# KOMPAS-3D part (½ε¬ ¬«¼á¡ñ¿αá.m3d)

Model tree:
1. Эскиз:1
2. Операция выдавливания:1
     Расстояние 1 = 4.8; Расстояние 2 = 0.3
3. Скругление:1
     Радиус = 14
4. Эскиз:3
5. Вырезать элемент выдавливания:1
     Расстояние 1 = 14.5
6. Эскиз:32
7. Операция выдавливания:21
     Расстояние 1 = 2; Расстояние 2 = 0.3
8. Эскиз:33
9. Операция выдавливания:22
     Расстояние 1 = 2; Расстояние 2 = 0.3
10. Эскиз:34
11. Операция выдавливания:23
     Расстояние 1 = 3; Расстояние 2 = 1
12. Эскиз:35
13. Вырезать элемент выдавливания:9
     Расстояние 1 = 35
14. Ломаная:2
15. Перпендикулярная плоскость:1
16. Эскиз:37
17. Вырезать кинематический элемент:1
     Толщина стенки 1 = 1; Толщина стенки 2 = 1
18. Эскиз:38
19. Вырезать элемент выдавливания:10
     Расстояние 1 = 0.3
20. Эскиз:39
21. Вырезать элемент выдавливания:11
     Расстояние 1 = 1.5
22. Эскиз:40
23. Операция выдавливания:24
     Расстояние 1 = 2; Расстояние 2 = 3.3
24. Эскиз:41
25. Вырезать элемент выдавливания:12
     Расстояние 1 = 1.5
26. Эскиз:42
27. Вырезать элемент выдавливания:13
     Расстояние 1 = 1.5
28. Эскиз:44
29. Вырезать элемент выдавливания:15
     Расстояние 1 = 10.5
30. Эскиз:45
31. Вырезать элемент выдавливания:16
     Расстояние 1 = 10.5
32. Скругление:4
     Радиус = 0.3
33. Скругление:5
     Радиус = 0.3
34. Скругление:6
     Радиус = 0.3
35. Скругление:7
     Радиус = 0.3
36. Эскиз:46
37. Вырезать элемент выдавливания:17
     Расстояние 1 = 7; Угол 1 = 48
38. Эскиз:47
39. Операция выдавливания:25
     Расстояние 1 = 2; Расстояние 2 = 3.3
40. Эскиз:48
41. Вырезать элемент выдавливания:18
     Расстояние 1 = 0.2; Угол 1 = 48
42. Эскиз:49
43. Вырезать элемент выдавливания:19
     Расстояние 1 = 0.2; Угол 1 = 48
44. Эскиз:50
45. Вырезать элемент выдавливания:20
     Расстояние 1 = 0.1; Угол 1 = 48
46. Скругление:8
     Радиус = 0.5
47. Эскиз:51
48. Операция выдавливания:26
     Расстояние 1 = 1; Расстояние 2 = 3.3
49. Эскиз:52
50. Операция выдавливания:27
     Расстояние 1 = 0.2; Расстояние 2 = 0.2
51. Эскиз:53
52. Операция выдавливания:28
     Расстояние 1 = 0.2; Расстояние 2 = 0.2
53. Эскиз:54
54. Операция выдавливания:29
     Расстояние 1 = 0.2; Расстояние 2 = 0.2
55. Ломаная:4
56. Перпендикулярная плоскость:2
57. Эскиз:55
58. Кинематическая операция:1
     Толщина стенки 1 = 1; Толщина стенки 2 = 1
59. Эскиз:56
60. Вырезать элемент выдавливания:21
     Расстояние 1 = 0.1; Угол 1 = 48
61. Скругление:10
     Радиус = 0.3
62. Скругление:11
     Радиус = 0.1

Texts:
  stalker61
  Сплав АЛ8  ГОСТ 1583-93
